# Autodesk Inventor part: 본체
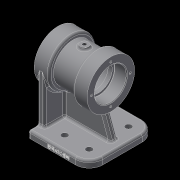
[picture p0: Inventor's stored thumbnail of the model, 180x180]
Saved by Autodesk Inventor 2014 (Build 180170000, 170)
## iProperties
Created: 2020-06
Part Number: 본체
Material: Generic
Document SubType Name: Modeling
Designer: kh
Density: 1 g/cm^3
Appearance: Default
Author: kh
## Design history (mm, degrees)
sketch "Sketch1"
  geometry: 1 further point
sketch "Sketch2"
  geometry: L1 (-45, 49)-(45, 49); L2 (45, 49)-(45, -49); L3 (45, -49)-(-45, -49); L4 (-45, -49)-(-45, 49); L5 (-45, 49)-(45, -49); L6 (45, 49)-(-45, -49); 1 further point
  constraints: 12 end point, 2 midpoint, 2 parallel, 1 horizontal, 1 perpendicular
  dimensions: "d0" = 90 distance of L1.start L1.end; "d1" = 98 distance of L1.end L2.end
extrude "Extrusion1" new body sketch "Sketch2" distance "d2" = 10; taper "d3" = 0 deg
sketch "Sketch4"
  geometry: L1 (-50, 105)-(-50, 70); L2 (-50, 70)-(28, 70); L3 (28, 70)-(28, 105); L4 (28, 105)-(6, 105); L5 (6, 105)-(6, 98.5); L6 (6, 98.5)-(-28, 98.5); L7 (-28, 98.5)-(-28, 105); L8 (-28, 105)-(-50, 105); L9 (-45, -10)-(45, -10) reference; 3 further points
  constraints: 16 end point, 4 parallel, 2 midpoint, 1 horizontal alignment, 1 perpendicular, 1 vertical
  dimensions: "d5" = 78 distance of L3.end L1.start; "d9" = 22 distance of L7.end L1.start; "d10" = 22 distance of L3.end L4.end; "d11" = 5 horizontal distance of L9.start L1.end; "d12" = 70 diameter of L8 L2; "d13" = 57 diameter of L6 L2; "d14" = 80 vertical distance of L9.end L2.end
revolve "Revolution1" sketch "Sketch4" stored, may be unused: angle "d15" = 90 deg
sketch "Sketch5"
  geometry: L1 (-45, 61.811)-(-45, 0); L2 (10.503, 61.811)-(33, 0); L3 (-45, 0)-(45, 0) reference; L4 (-45, 61.811)-(10.503, 61.811); L5 (-45, 0)-(33, 0); L6 (-50, 35)-(-50, 105) reference; 1 further point
  constraints: 8 end point, 2 point on line, 1 parallel, 1 perpendicular, 1 vertical
  dimensions: "d16" = 70 deg angle of L2 L3; "d17" = 5 distance from line of L1.end L6; "d18" = 12 distance of L3.end L2.end
extrude "Extrusion2" join sketch "Sketch5" stored distance "d19" = 10; taper "d20" = 0 deg
sketch "Sketch6"
  geometry: L1 (-45, 35)-(-35, 35); L2 (-35, 35)-(-35, -35); L3 (-35, -35)-(-45, -35); L4 (-45, -35)-(-45, 35); 3 further points
  constraints: 8 end point, 2 parallel, 1 horizontal, 1 horizontal alignment, 1 midpoint, 1 perpendicular, 1 vertical alignment
  dimensions: "d21" = 70 distance between parallel lines of L3 L1; "d22" = 10 horizontal distance of point (-45, 49) L1.end
extrude "Extrusion3" join sketch "Sketch6" distance "d23" = 70; taper "d24" = 0 deg
sketch "Sketch7"
  geometry: L1 (45, 49)-(45, -49) reference; 8 further points
  constraints: 3 horizontal alignment, 2 vertical alignment, 1 midpoint
  dimensions: "d25" = 36 distance of point (25, 29) point (-11, 29); "d26" = 70 horizontal distance of point (25, 29) point (-45, 49); "d27" = 58 distance of point (25, -29) point (25, 29)
hole "Hole1" sketch "Sketch7" at (-11, 29), (25, 29), (25, -29), (-11, -29) diameter "d28" = 9; stored, may be unused: countersink angle "d32" = 90 deg, drill point angle "d34" = 118 deg; dims "d29" = 6, "d30" = 4, "d31" = 2, "d33" = 8
sketch "Sketch8"
  geometry: L1 (-50, 70)-(28, 70); L2 (-50, 35)-(-50, 105) reference; L3 (28, 35)-(28, 105) reference; L4 (-50, 70)-(-50, 93.5); L5 (-50, 93.5)-(-32, 93.5); L6 (-32, 93.5)-(-32, 90); L7 (-32, 90)-(-26, 90); L8 (-26, 90)-(-26, 93); L9 (-26, 93)-(4, 93); L10 (4, 93)-(4, 90); L11 (4, 90)-(10, 90); L12 (10, 90)-(10, 93.5); L13 (10, 93.5)-(28, 93.5); L14 (28, 70)-(28, 93.5); 4 further points
  constraints: 24 end point, 6 parallel, 5 midpoint, 4 perpendicular, 3 point on line, 1 horizontal, 1 horizontal alignment
  dimensions: "d35" = 47 diameter of L5 L1; "d36" = 40 diameter of L7 L1; "d37" = 18 distance of L4.end L5.end; "d38" = 6 distance of L6.end L7.end; "d39" = 30 distance of L8.end L9.end; "d40" = 18 distance of L12.end L13.end; "d41" = 47 diameter of L13 L1; "d42" = 46 diameter of L9 L1
revolve "Revolution2" sketch "Sketch8" stored, may be unused: angle "d43" = 90 deg
workplane "Work Plane2"
sketch "Sketch9"
  geometry: L1 (-50, -35)-(-50, 35) reference; C1 r 6 at (-11, 0); 2 further points
  constraints: 1 centre point, 1 coincident, 1 horizontal alignment
  dimensions: "d45" = 39 distance from line of point (-11, 0) L1; "d46" = 12 diameter of C1
extrude "Extrusion4" join sketch "Sketch9" stored distance "d47" = 70; taper "d48" = 0 deg
hole "Hole2" diameter "d51" = 5.188; stored, may be unused: countersink angle "d55" = 90 deg, drill point angle "d57" = 118 deg; dims "d49" = 10, "d50" = 10, "d52" = 6, "d53" = 4, "d54" = 2, "d56" = 8
sketch "Sketch10"
  geometry: C1 r 23.5 at (0, 0) reference; 2 further points
  constraints: 1 vertical alignment
  dimensions: "d59" = 28.5 distance of C1.centre point (0, 28.5)
hole "Hole3" sketch "Sketch10" at (0, 28.5) diameter "d60" = 3.242; stored, may be unused: countersink angle "d64" = 90 deg, drill point angle "d66" = 118 deg; dims "d61" = 10, "d62" = 4, "d63" = 2, "d65" = 12
pattern_circular "Circular Pattern1" dims angle "d68" = 360 deg
workplane "Work Plane3"
mirror "Mirror1"
fillet "Fillet1" dims "d70" = 3
fillet "Fillet2" dims "d71" = 3
fillet "Fillet5" dims "d74" = 3
sketch "Sketch11"
  geometry: L1 (-3, 7)-(-3, 0) reference; 3 further points
  constraints: 1 other
  dimensions: "d75" = 4 vertical distance of point (0, 0) point (42, 4); "d76" = 45 distance from line of point (42, 4) L1
emboss "Emboss1" sketch "Sketch11" dims "d0" = 90, "d1" = 98, "d77" = 0.5, "d78" = 0
chamfer "Chamfer1" distance "d79" = 1; stored, may be unused: second distance "d80" = 2, angle "d81" = 45 deg
fillet "Fillet6" dims "d82" = 20, "d83" = 3
fillet "Fillet7" dims "d84" = 3
fillet "Fillet8" dims "d85" = 3
fillet "Fillet9" dims "d86" = 0.3
body "Solid1"
other parameters: "d44" = -111.5
